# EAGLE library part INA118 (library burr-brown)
Instrumentation Amplifier Precision, Low Power
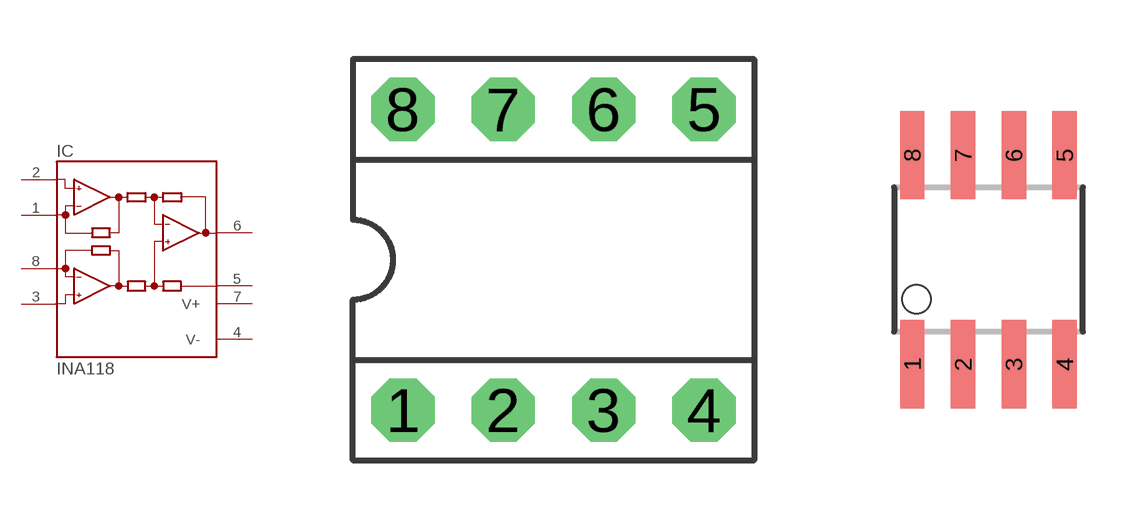
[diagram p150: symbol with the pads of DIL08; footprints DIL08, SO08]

Designator prefix IC

## INA118P (MF: TEXAS INSTRUMENTS; MPN: INA118P; OC_FARNELL: 1470354; OC_NEWARK: 96K4515)  [DIL08]
1  RG  pas
2  -IN  in
3  +IN  in
4  V-  pwr
5  REF  pas
6  OUT  out
7  V+  pwr
8  RG  pas

## INA118U (MF: TEXAS INSTRUMENTS; MPN: INA118U; OC_FARNELL: 1212404; OC_NEWARK: 04M6168)  [SO08]
Pads as for DIL08

## Footprint DIL08 (pad centres in mm)
Dual In Line
drill 0.813 pad 1.6 octagon: 1 -3.81,-3.81; 2 -1.27,-3.81; 3 1.27,-3.81; 4 3.81,-3.81; 5 3.81,3.81; 6 1.27,3.81; 7 -1.27,3.81; 8 -3.81,3.81

## Footprint SO08 (pad centres in mm)
Small Outline Package
smd 0.61 x 2.21: 1 -1.905,-2.616; 2 -0.635,-2.616; 3 0.635,-2.616; 4 1.905,-2.616; 5 1.905,2.616; 6 0.635,2.616; 7 -0.635,2.616; 8 -1.905,2.616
